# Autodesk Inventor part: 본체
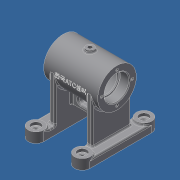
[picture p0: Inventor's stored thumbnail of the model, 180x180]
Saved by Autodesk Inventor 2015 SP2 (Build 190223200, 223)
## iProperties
Created: 2015-11
Part Number: 본체
Material: 일반
Document SubType Name: Modeling
Designer: AMC
Density: 1 g/cm^3
Appearance: 기본값
Author: AMC
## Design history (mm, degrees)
sketch "스케치1"
  geometry: C1 r 25 at (0, 0); 1 further point
  constraints: 1 centre point, 1 coincident
  dimensions: "d0" = 50 diameter of C1
extrude "돌출1" new body sketch "스케치1" stored distance "d1" = 70; taper "d2" = 0 deg
node "작업 평면1"
sketch "스케치2"
  geometry: C1 r 5 at (0, 0); 1 further point
  constraints: 1 centre point, 1 coincident
  dimensions: "d4" = 10 diameter of C1
extrude "돌출2" join sketch "스케치2" stored distance "d5" = 70; taper "d6" = 0 deg
node "작업 평면2"
sketch "스케치3"
  geometry: L1 (25, 0)-(-25, 0); L2 (-25, 0)-(-25, -68); L3 (-25, -68)-(25, -68); L4 (25, -68)-(25, 0); L5 (0, 0)-(0, 5.329)
  constraints: 10 end point, 2 parallel, 1 horizontal, 1 midpoint, 1 perpendicular, 1 vertical, 1 other
  dimensions: "d8" = 50 distance of L1.start L1.end; "d11" = 68 distance from line of L3 L5.start
extrude "돌출3" join sketch "스케치3" distance "d12" = 8; taper "d13" = 0 deg
sketch "스케치4"
  geometry: L1 (65, 10)-(-15, 10); L2 (65, 20)-(-15, 20); L3 (-15, 0)-(65, 0); L4 (0, 0)-(50, 0) reference; A1 r 10 centre (65, 10) between (65, 0) and (65, 20); A2 r 10 centre (-15, 10) between (-15, 20) and (-15, 0); 2 further points
  constraints: 8 end point, 4 point on circle, 4 tangent, 2 centre point, 1 collinear, 1 horizontal, 1 midpoint, 1 parallel
  dimensions: "d14" = 80 distance of L1.start L1.end; "d16" = 20 diameter of A1; "d17" = 40 horizontal distance of L1.start point (25, -20)
extrude "돌출4" join sketch "스케치4" distance "d18" = 10; taper "d19" = 0 deg
sketch "스케치6"
  geometry: C1 r 10 at (-65, 10); C2 r 10 at (15, 10); C3 r 10 at (15, -50); C4 r 10 at (-65, -50); A1 r 10 centre (-65, 10) between (-65, 20) and (-65, 0) reference; A2 r 10 centre (15, 10) between (15, 0) and (15, 20) reference; A3 r 10 centre (15, -50) between (15, -60) and (15, -40) reference; A4 r 10 centre (-65, -50) between (-65, -40) and (-65, -60) reference; 1 further point
  constraints: 4 centre point, 4 concentric
  dimensions: "d29" = 20 diameter of C1; "d32" = 20 diameter of C2; "d33" = 20 diameter of C3; "d34" = 20 diameter of C4
extrude "돌출6" join sketch "스케치6" distance "d30" = 3; taper "d31" = 0 deg
node "작업 평면5"
  node "작업 평면4"
sketch "스케치7"
  geometry: 1 further point
sketch "스케치8"
  geometry: C1 r 6 at (0, 0); 1 further point
  constraints: 1 centre point, 1 coincident
  dimensions: "d37" = 12 diameter of C1
extrude "돌출7" join sketch "스케치8" stored distance "d38" = 3; taper "d39" = 0 deg
hole "구멍1" diameter "d42" = 32; stored, may be unused: countersink angle "d46" = 90 deg, drill point angle "d48" = 0 deg; dims "d43" = 6, "d44" = 4, "d45" = 2, "d47" = 12, "d51" = 10, "d52" = 10
hole "구멍2" diameter "d53" = 32; stored, may be unused: countersink angle "d57" = 90 deg, drill point angle "d59" = 0 deg; dims "d49" = 10, "d50" = 10, "d54" = 6, "d55" = 4, "d56" = 2, "d58" = 12
hole "구멍3" diameter "d62" = 28; stored, may be unused: countersink angle "d66" = 90 deg, drill point angle "d68" = 0 deg; dims "d63" = 6, "d64" = 4, "d65" = 2, "d67" = 2, "d69" = 10, "d70" = 10
hole "구멍4" diameter "d73" = 28; stored, may be unused: countersink angle "d77" = 90 deg, drill point angle "d79" = 0 deg; dims "d71" = 10, "d72" = 10, "d74" = 6, "d75" = 4, "d76" = 2, "d78" = 2
hole "구멍5" diameter "d82" = 42; stored, may be unused: countersink angle "d86" = 90 deg, drill point angle "d88" = 0 deg; dims "d80" = 10, "d81" = 10, "d83" = 6, "d84" = 4, "d85" = 2, "d87" = 42
hole "구멍6" diameter "d91" = 6; stored, may be unused: countersink angle "d95" = 90 deg, drill point angle "d97" = 0 deg; dims "d92" = 6, "d93" = 12, "d94" = 4, "d96" = 42, "d127" = 10, "d128" = 10
hole "구멍7" diameter "d100" = 6; stored, may be unused: countersink angle "d104" = 90 deg, drill point angle "d106" = 0 deg; dims "d98" = 10, "d99" = 10, "d101" = 6, "d102" = 12, "d103" = 4, "d105" = 42
hole "구멍8" diameter "d109" = 6; stored, may be unused: countersink angle "d113" = 90 deg, drill point angle "d115" = 0 deg; dims "d107" = 10, "d108" = 10, "d110" = 6, "d111" = 12, "d112" = 4, "d114" = 42
hole "구멍9" diameter "d118" = 6; stored, may be unused: countersink angle "d122" = 90 deg, drill point angle "d124" = 0 deg; dims "d116" = 10, "d117" = 10, "d119" = 6, "d120" = 12, "d121" = 4, "d123" = 42
hole "구멍10" diameter "d129" = 4.917; stored, may be unused: countersink angle "d133" = 90 deg, drill point angle "d135" = 0 deg; dims "d125" = 10, "d126" = 10, "d130" = 12, "d131" = 1, "d132" = 4, "d134" = 17.1
hole "구멍11" diameter "d138" = 4.917; stored, may be unused: countersink angle "d142" = 90 deg, drill point angle "d144" = 0 deg; dims "d136" = 10, "d137" = 10, "d139" = 12, "d140" = 1, "d141" = 4, "d143" = 17.1
sketch "스케치9" dims "d145" = 40
  geometry: 3 further points
  constraints: 1 coincident, 1 vertical alignment, 2 other
hole "구멍12" sketch "스케치9" at (0, -20) diameter "d146" = 3.459; stored, may be unused: countersink angle "d150" = 90 deg, drill point angle "d152" = 118 deg; dims "d147" = 8, "d148" = 1, "d149" = 4, "d151" = 10
node "작업 평면7"
sketch "스케치10"
  geometry: L1 (-20.739, 3.002)-(20.739, 3.002); L2 (20.739, 3.002)-(20.739, -3.002); L3 (20.739, -3.002)-(-20.739, -3.002); L4 (-20.739, -3.002)-(-20.739, 3.002); L5 (-20.739, 0)-(20.739, 0); L6 (0, 3.002)-(0, -3.002); L7 (20, -25)-(-20, -25) reference; L8 (-35, 25)-(-35, -25) reference; 1 further point
  constraints: 4 end point, 4 midpoint, 2 other
  dimensions: "d157" = 41.47897 distance of L1.start L1.end; "d158" = 6.00407 distance of L1.end L2.end; "d159" = 25 distance between parallel lines of L5 L7; "d160" = 35 distance between parallel lines of L8 L6
feature "엠보싱1" sketch "스케치10" dims "d161" = 0.5, "d162" = 0
fillet "모깎기1" dims "d163" = 0.3
fillet "모깎기2" dims "d164" = 0.3
chamfer "모따기1" distance "d165" = 1; stored, may be unused: second distance "d166" = 2, angle "d167" = 45 deg
chamfer "모따기2" distance "d168" = 1; stored, may be unused: second distance "d169" = 2, angle "d170" = 45 deg
fillet "모깎기5" dims "d173" = 2
fillet "모깎기7" dims "d175" = 2
fillet "모깎기8" dims "d176" = 2
fillet "모깎기10" dims "d178" = 2
fillet "모깎기11" dims "d179" = 2
sketch "스케치11"
  geometry: L1 (-20, -22.177)-(20, -22.177); L2 (20, -22.177)-(20, -45); L3 (20, -45)-(-20, -45); L4 (-20, -45)-(-20, -22.177); L5 (-20, -14.142)-(-20, -56) reference; L6 (20, -56)-(20, -14.142) reference; L7 (-8, -35)-(8, -35); L8 (-8, -31.5)-(8, -31.5); L9 (8, -38.5)-(-8, -38.5); A1 r 3.5 centre (-8, -35) between (-8, -31.5) and (-8, -38.5); A2 r 3.5 centre (8, -35) between (8, -38.5) and (8, -31.5); 2 further points
  constraints: 16 end point, 4 point on circle, 4 tangent, 3 parallel, 2 centre point, 2 collinear, 2 horizontal, 1 midpoint, 1 perpendicular
  dimensions: "d182" = 3.5 radius of A2; "d183" = 23 dimension on A1 A2; "d185" = 45 distance from line of point (0, 0) L3; "d186" = 10 distance between parallel lines of L3 L7
extrude "돌출8" join sketch "스케치11" stored distance "d187" = 8; taper "d188" = 0 deg
fillet "모깎기12" dims "d189" = 2
fillet "모깎기13" dims "d190" = 2
fillet "모깎기14" dims "d191" = 3
node "솔리드1"
mirror "대칭1"
mirror "대칭2"
pattern_circular "원형 패턴1" dims angle "d154" = 360 deg
mirror "대칭3"
node "작업 평면3"
node "작업 평면6"
other parameters: "d3" = 28, "d35" = -30 deg, "d36" = -28, "d156" = -53.5
